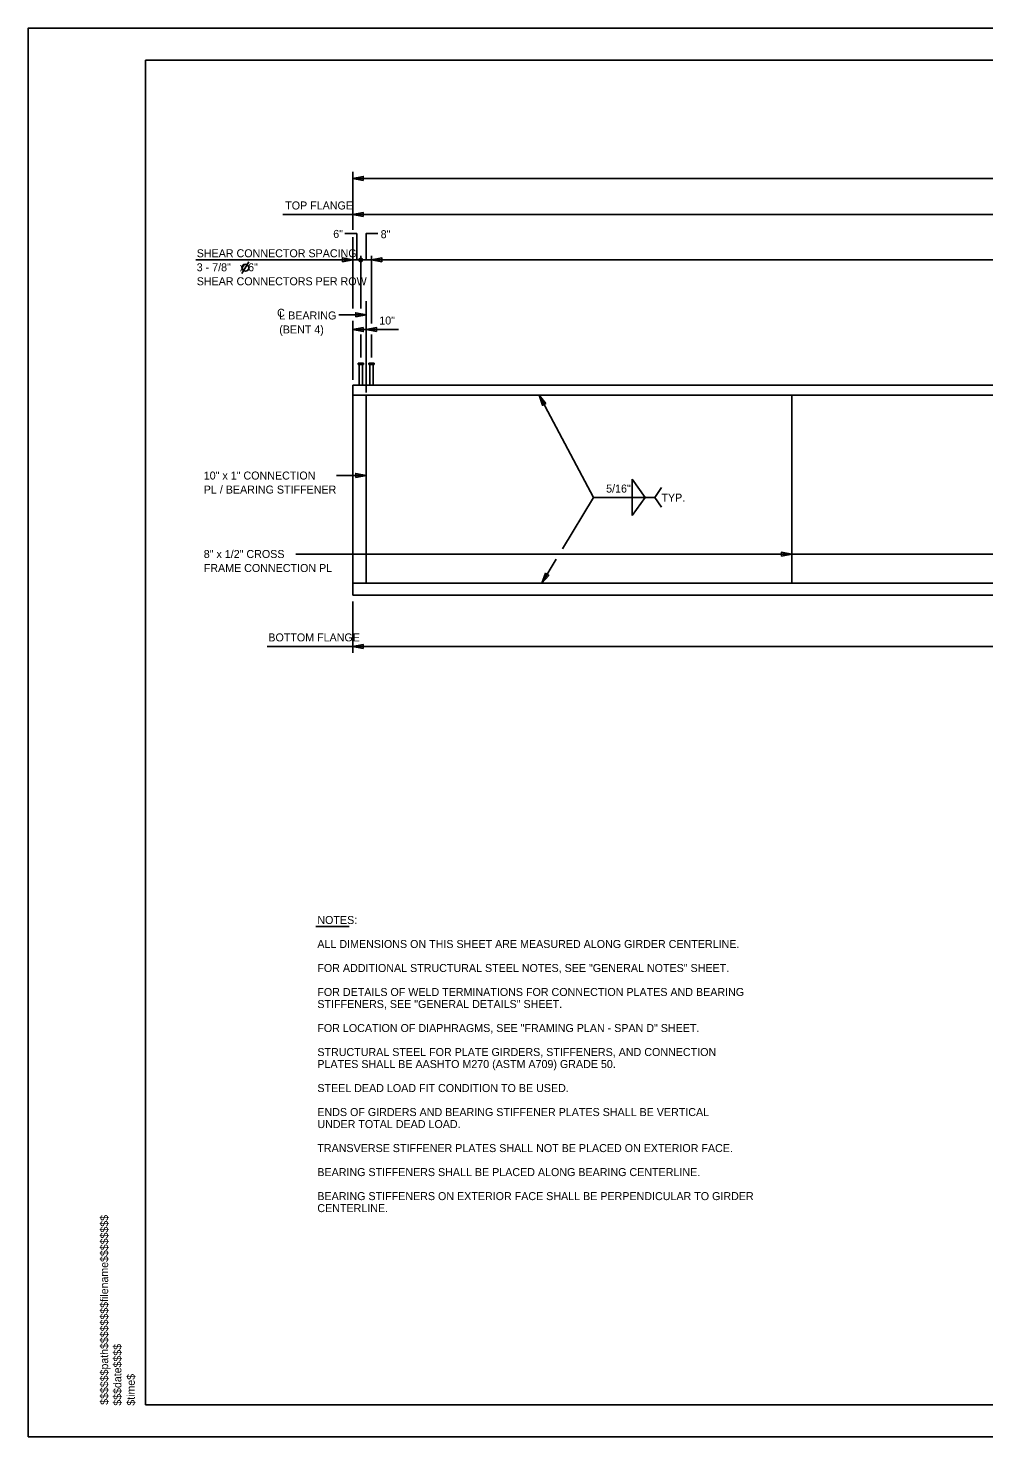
# Model space of a CAD drawing. Extents: x -305 to -161, y -187 to -99.
# Drawn here: x -305.2 to -245.4, y -187.5 to -99.5 of the extents above; entities that cross this region are included whole.
import ezdxf

# ---------------------------------------------------------------- set-up
doc = ezdxf.new("R2010")
doc.units = 0
for name, color, linetype in [('BR_AUTO DIMENSION', 7, 'Continuous'), ('BR_BORDER LINES', 7, 'Continuous'), ('BR_CENTER LINES', 7, 'Continuous'), ('BR_STRUCTURAL STEEL', 7, 'Continuous'), ('BR_TEXT', 7, 'Continuous'), ('Default', 7, 'Continuous'), ('Level 31', 7, 'Continuous'), ('RD_SHT_ID', 7, 'Continuous')]:
    doc.layers.add(name, color=color, linetype=linetype)

msp = doc.modelspace()

# ---------------------------------------------------------------- linework, layer by layer
at = {"layer": 'BR_AUTO DIMENSION'}
for p, q in [((-284.888, -112.096), (-284.888, -108.463)), ((-284.888, -108.876), (-176.804, -108.876)), ((-284.888, -111.134), (-289.258, -111.134)), ((-284.888, -111.134), (-176.804, -111.134)), ((-284.888, -116.993), (-284.888, -112.544)), ((-284.888, -113.971), (-294.705, -113.971)), ((-283.721, -113.971), (-284.888, -113.971)), ((-284.388, -116.993), (-284.388, -113.71)), ((-283.721, -117.94), (-283.721, -113.71)), ((-177.888, -113.971), (-283.721, -113.971)), ((-284.055, -117.397), (-285.757, -117.397)), ((-284.888, -121.468), (-284.888, -117.764)), ((-284.888, -118.321), (-282.036, -118.321)), ((-284.388, -120.06), (-284.388, -118.631)), ((-283.721, -120.06), (-283.721, -118.631)), ((-269.841, -128.801), (-273.229, -122.412)), ((-284.055, -127.431), (-285.903, -127.431)), ((-267.425, -127.667), (-267.425, -129.935)), ((-267.425, -127.667), (-266.619, -128.801)), ((-266.016, -128.801), (-265.583, -128.194)), ((-269.841, -128.801), (-271.787, -132.021)), ((-269.841, -128.801), (-266.016, -128.801)), ((-267.425, -129.935), (-266.619, -128.801)), ((-266.016, -128.801), (-265.583, -129.408)), ((-204.242, -132.351), (-288.443, -132.351)), ((-272.174, -132.66), (-273.082, -134.162)), ((-284.888, -135.312), (-284.888, -138.518)), ((-284.888, -138.117), (-290.236, -138.117)), ((-284.888, -138.117), (-176.804, -138.117)), ((-287.194, -155.612), (-285.117, -155.612))]:
    msp.add_line(p, q, dxfattribs=at)
for points in [[(-284.238, -109.001), (-284.888, -108.876), (-284.238, -108.751)], [(-284.238, -111.259), (-284.888, -111.134), (-284.238, -111.009)], [(-285.538, -114.096), (-284.888, -113.971), (-285.538, -113.846)], [(-283.071, -114.096), (-283.721, -113.971), (-283.071, -113.846)], [(-284.705, -117.522), (-284.055, -117.397), (-284.705, -117.272)], [(-284.238, -118.196), (-284.888, -118.321), (-284.238, -118.446)], [(-283.405, -118.446), (-284.055, -118.321), (-283.405, -118.196)], [(-272.814, -122.928), (-273.229, -122.412), (-273.035, -123.045)], [(-284.705, -127.556), (-284.055, -127.431), (-284.705, -127.306)], [(-258.1, -132.476), (-257.45, -132.351), (-258.1, -132.226)], [(-272.852, -133.541), (-273.082, -134.162), (-272.639, -133.671)], [(-284.238, -138.242), (-284.888, -138.117), (-284.238, -137.992)]]:
    msp.add_lwpolyline(points, close=True, dxfattribs=at)
for points in [[(-284.638, -113.971), (-284.638, -112.325), (-285.378, -112.325)], [(-284.055, -113.971), (-284.055, -112.325), (-283.315, -112.325)]]:
    msp.add_lwpolyline(points, dxfattribs=at)
msp.add_circle((-284.388, -113.971), 0.111, dxfattribs=at)
at = {"layer": 'BR_BORDER LINES'}
for p, q in [((-163.178, -101.489), (-297.843, -101.489)), ((-297.843, -185.489), (-297.843, -101.489)), ((-297.843, -185.489), (-163.178, -185.489))]:
    msp.add_line(p, q, dxfattribs=at)
at = {"layer": 'BR_CENTER LINES'}
msp.add_line((-284.055, -116.535), (-284.055, -122.256), dxfattribs=at)
at = {"layer": 'BR_STRUCTURAL STEEL'}
for p, q in [((-284.888, -121.787), (-176.804, -121.787)), ((-284.888, -121.787), (-284.888, -122.412)), ((-284.888, -122.412), (-176.804, -122.412)), ((-284.888, -122.412), (-284.888, -134.162)), ((-284.055, -122.412), (-284.055, -134.162)), ((-257.45, -122.412), (-257.45, -134.162)), ((-284.888, -134.162), (-176.804, -134.162)), ((-284.888, -134.162), (-284.888, -134.912)), ((-284.888, -134.912), (-176.804, -134.912))]:
    msp.add_line(p, q, dxfattribs=at)
at = {"layer": 'BR_TEXT'}
msp.add_line((-291.812, -114.817), (-291.392, -114.089), dxfattribs=at)
msp.add_circle((-291.602, -114.453), 0.22, dxfattribs=at)
at = {"layer": 'Default'}
for p, q in [((-284.56, -120.412), (-284.56, -120.506)), ((-284.56, -120.412), (-284.216, -120.412)), ((-284.56, -120.506), (-284.216, -120.506)), ((-284.497, -120.506), (-284.497, -121.787)), ((-284.279, -120.506), (-284.279, -121.787)), ((-284.216, -120.412), (-284.216, -120.506)), ((-283.893, -120.412), (-283.893, -120.506)), ((-283.893, -120.412), (-283.55, -120.412)), ((-283.893, -120.506), (-283.55, -120.506)), ((-283.831, -120.506), (-283.831, -121.787)), ((-283.612, -120.506), (-283.612, -121.787)), ((-283.55, -120.412), (-283.55, -120.506))]:
    msp.add_line(p, q, dxfattribs=at)
at = {"layer": 'Level 31'}
msp.add_lwpolyline([(-305.176, -187.489), (-161.176, -187.489), (-161.176, -99.489), (-305.176, -99.489)], close=True, dxfattribs=at)

# ---------------------------------------------------------------- texts
at = {"layer": 'BR_AUTO DIMENSION'}
for s, p in [('TOP FLANGE', (-289.11, -110.815)), ('6"', (-286.11, -112.593)), ('8"', (-283.144, -112.609)), ('10"', (-283.233, -118.002)), ('5/16"', (-269.053, -128.501)), ('TYP.', (-265.599, -129.067)), ('BOTTOM FLANGE', (-290.164, -137.798)), ('NOTES:', (-287.102, -155.451)), ('ALL DIMENSIONS ON THIS SHEET ARE MEASURED ALONG GIRDER CENTERLINE.', (-287.102, -156.951)), ('FOR ADDITIONAL STRUCTURAL STEEL NOTES, SEE "GENERAL NOTES" SHEET.', (-287.102, -158.451)), ('FOR DETAILS OF WELD TERMINATIONS FOR CONNECTION PLATES AND BEARING ', (-287.102, -159.951)), ('STIFFENERS, SEE "GENERAL DETAILS" SHEET.', (-287.102, -160.701)), ('FOR LOCATION OF DIAPHRAGMS, SEE "FRAMING PLAN - SPAN D" SHEET.', (-287.102, -162.201)), ('STRUCTURAL STEEL FOR PLATE GIRDERS, STIFFENERS, AND CONNECTION ', (-287.102, -163.701)), ('PLATES SHALL BE AASHTO M270 (ASTM A709) GRADE 50.', (-287.102, -164.451)), ('STEEL DEAD LOAD FIT CONDITION TO BE USED.', (-287.102, -165.951)), ('ENDS OF GIRDERS AND BEARING STIFFENER PLATES SHALL BE VERTICAL', (-287.102, -167.451)), ('UNDER TOTAL DEAD LOAD.', (-287.102, -168.201)), ('TRANSVERSE STIFFENER PLATES SHALL NOT BE PLACED ON EXTERIOR FACE.', (-287.102, -169.701)), ('BEARING STIFFENERS SHALL BE PLACED ALONG BEARING CENTERLINE.', (-287.102, -171.201)), ('BEARING STIFFENERS ON EXTERIOR FACE SHALL BE PERPENDICULAR TO GIRDER', (-287.102, -172.701)), ('CENTERLINE.', (-287.102, -173.451))]:
    msp.add_text(s, height=0.5, rotation=360, dxfattribs=at).set_placement(p)
at = {"layer": 'BR_TEXT'}
for s, p in [('SHEAR CONNECTOR SPACING', (-294.641, -113.801)), ('3 - 7/8"   x 6" ', (-294.641, -114.676)), ('SHEAR CONNECTORS PER ROW', (-294.641, -115.551)), ('C', (-289.618, -117.52)), ('L BEARING', (-289.483, -117.686)), ('(BENT 4)', (-289.483, -118.561)), ('10" x 1" CONNECTION ', (-294.201, -127.688)), ('PL / BEARING STIFFENER', (-294.201, -128.563)), ('8" x 1/2" CROSS ', (-294.201, -132.588)), ('FRAME CONNECTION PL', (-294.201, -133.463))]:
    msp.add_text(s, height=0.5, rotation=360, dxfattribs=at).set_placement(p)
at = {"layer": 'RD_SHT_ID'}
for s, height, p in [('$$$$$$path$$$$$$$$filename$$$$$$$$', 0.49387, (-300.176, -185.489)), ('$$$date$$$$', 0.49387, (-299.353, -185.542)), ('$time$', 0.4939, (-298.509, -185.542))]:
    msp.add_text(s, height=height, rotation=90, dxfattribs=at).set_placement(p)

doc.saveas('drawing.dxf')
